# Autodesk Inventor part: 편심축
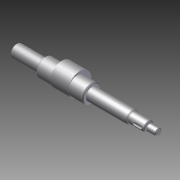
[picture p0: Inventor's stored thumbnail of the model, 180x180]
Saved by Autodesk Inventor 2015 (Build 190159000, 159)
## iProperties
Created: 2025-08
Part Number: 편심축
Material: 일반
Document SubType Name: Modeling
Designer: user
Density: 1 g/cm^3
Appearance: 기본값
Author: user
Author: jhkim
Creation Date: 2025-08-05
Sending System: Autodesk Inventor 2026
Preprocessor: ST-DEVELOPER v20.1
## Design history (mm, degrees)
node "편심축1"
node "솔리드1"
node "기준1"
